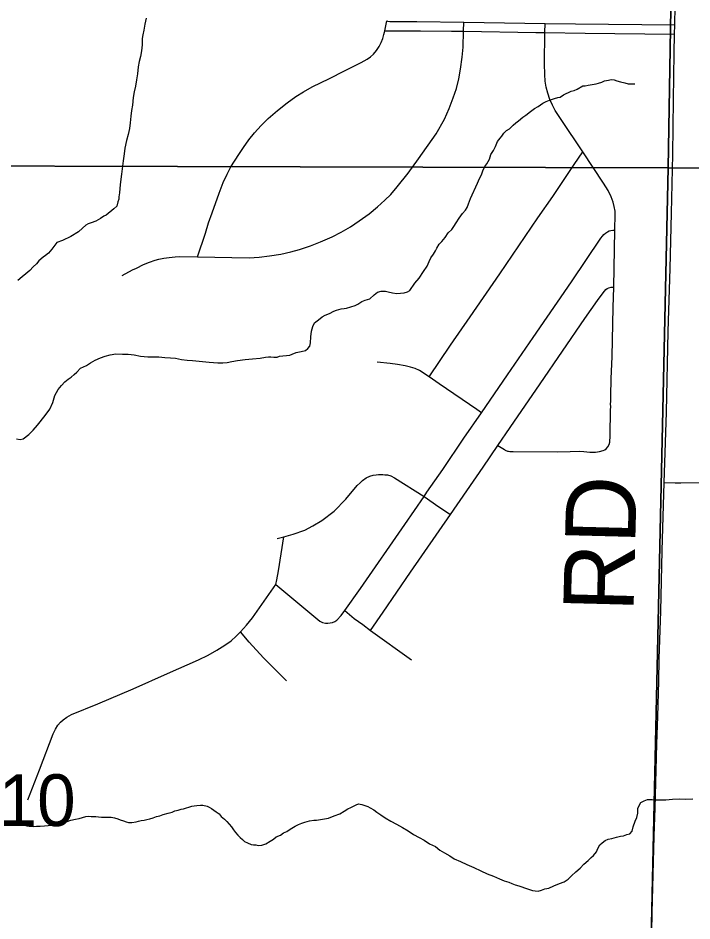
# Model space of a CAD drawing. Extents: x 2.4 to 73.1, y 4.5 to 25.6.
# Drawn here: x 35.324 to 35.5963, y 23.7807 to 24.1457 of the extents above; entities that cross this region are included whole.
import ezdxf

# ---------------------------------------------------------------- set-up
doc = ezdxf.new("R2010")
doc.units = 0
for name, color, linetype in [('GM_X_Minor_River', 7, 'Continuous'), ('GM_X_Section', 7, 'Continuous'), ('GM_X_Section_Text', 7, 'Continuous'), ('GM_X_Township_Road', 7, 'Continuous'), ('GM_X_Township_Road_Text', 7, 'Continuous')]:
    doc.layers.add(name, color=color, linetype=linetype)

msp = doc.modelspace()

# ---------------------------------------------------------------- linework, layer by layer
at = {"layer": 'GM_X_Minor_River'}
for points in [[(35.37569, 24.14575), (35.37525, 24.14329), (35.37481, 24.14083), (35.37438, 24.13895), (35.37415, 24.13743), (35.37409, 24.13497), (35.37384, 24.1325), (35.3734, 24.13024), (35.37297, 24.12816), (35.37254, 24.12608), (35.37228, 24.12324), (35.37183, 24.12078), (35.37139, 24.11814), (35.37095, 24.11587), (35.37051, 24.1136), (35.37025, 24.11057), (35.36981, 24.1083), (35.36956, 24.10603), (35.36931, 24.10338), (35.36906, 24.10111), (35.36843, 24.09865), (35.3678, 24.0962), (35.36715, 24.09318), (35.3669, 24.09091), (35.36645, 24.08807), (35.36621, 24.0858), (35.36575, 24.08258), (35.36526, 24.07842)], [(35.506, 24.07067), (35.50681, 24.07274), (35.50963, 24.07893), (35.51043, 24.08081), (35.51123, 24.08231), (35.51184, 24.084), (35.51265, 24.08569), (35.51343, 24.08681), (35.51443, 24.08868), (35.51505, 24.09057), (35.51604, 24.09225), (35.51684, 24.09375), (35.51765, 24.09582), (35.51882, 24.09712), (35.51941, 24.09805), (35.5202, 24.09917), (35.52137, 24.10028), (35.52253, 24.10101), (35.52409, 24.10249), (35.52506, 24.10341), (35.52622, 24.10415), (35.52796, 24.10562), (35.52913, 24.10654), (35.53106, 24.10801), (35.53261, 24.10911), (35.53415, 24.11002), (35.53608, 24.1113), (35.53743, 24.11202), (35.53877, 24.11256), (35.54069, 24.11327), (35.54203, 24.11362), (35.54298, 24.11378), (35.54434, 24.1147), (35.54549, 24.11524), (35.54645, 24.11559), (35.54741, 24.11614), (35.54875, 24.11649), (35.5499, 24.11702), (35.55221, 24.1183), (35.55316, 24.11827), (35.55431, 24.11862), (35.55755, 24.11911), (35.55851, 24.11947), (35.55985, 24.11981), (35.561, 24.12035), (35.56253, 24.12069), (35.56367, 24.12085), (35.56481, 24.12082), (35.56594, 24.12042), (35.56745, 24.12), (35.56915, 24.11958), (35.57047, 24.11916), (35.5718, 24.11913), (35.5732, 24.11909)], [(35.36526, 24.07842), (35.36498, 24.07501), (35.36476, 24.07349), (35.36473, 24.07255), (35.36432, 24.07142), (35.3639, 24.06972), (35.36273, 24.06861), (35.35963, 24.06603), (35.35867, 24.06567), (35.35732, 24.06476), (35.35539, 24.06367), (35.35347, 24.06296), (35.35233, 24.06261), (35.35136, 24.06206), (35.35, 24.06077), (35.34844, 24.05929), (35.34536, 24.05747), (35.3419, 24.05585), (35.3396, 24.05496), (35.33763, 24.05235), (35.33626, 24.05067), (35.3351, 24.04975), (35.33413, 24.04902), (35.33238, 24.04754), (35.3314, 24.04643), (35.33004, 24.04514), (35.32867, 24.04365), (35.32712, 24.04236), (35.32557, 24.04107), (35.32382, 24.0396)], [(35.34428, 23.99978), (35.34544, 24.00051), (35.34661, 24.00162), (35.34777, 24.00254), (35.34914, 24.00421), (35.35164, 24.00529), (35.35319, 24.00639), (35.35511, 24.00748), (35.35723, 24.00837), (35.35914, 24.00908), (35.36125, 24.0096), (35.36353, 24.00992), (35.36619, 24.00985), (35.36847, 24.00979), (35.37093, 24.00954), (35.37339, 24.0091), (35.37642, 24.00883), (35.37851, 24.00878), (35.38079, 24.00872), (35.38325, 24.00847), (35.38553, 24.00841), (35.38761, 24.00817), (35.39007, 24.00773), (35.39234, 24.00748), (35.39442, 24.00724), (35.40125, 24.00668), (35.40466, 24.00641), (35.40675, 24.00636), (35.40846, 24.0065), (35.41037, 24.00683), (35.41266, 24.00734), (35.41571, 24.00765), (35.41876, 24.00795), (35.4218, 24.00825), (35.4239, 24.00858), (35.42523, 24.00874), (35.42618, 24.00871), (35.42732, 24.00868), (35.42865, 24.00865), (35.42961, 24.009), (35.43094, 24.00916), (35.43246, 24.00931), (35.4338, 24.00947), (35.43476, 24.00982), (35.4363, 24.01054), (35.43839, 24.01087), (35.44012, 24.01139), (35.44108, 24.01213), (35.44187, 24.01306), (35.44209, 24.01438), (35.44234, 24.01684), (35.44259, 24.01912), (35.4428, 24.02006), (35.44302, 24.021), (35.44381, 24.0225), (35.44537, 24.02379), (35.44691, 24.02489), (35.44807, 24.02562), (35.4498, 24.02634), (35.45153, 24.02724), (35.45268, 24.02759), (35.45459, 24.02811), (35.45574, 24.02828), (35.45669, 24.02844), (35.46014, 24.02949), (35.46129, 24.03003), (35.46284, 24.03113), (35.46418, 24.03167), (35.46609, 24.03219), (35.46784, 24.03385), (35.4692, 24.03496), (35.47073, 24.0353), (35.47244, 24.03526), (35.47357, 24.03504), (35.47527, 24.03461), (35.47697, 24.03438), (35.4785, 24.03453), (35.48002, 24.03468), (35.48136, 24.03503), (35.48232, 24.03557), (35.4843, 24.03856), (35.48606, 24.04061), (35.48783, 24.04322), (35.48922, 24.04546), (35.49003, 24.04734), (35.49082, 24.04884), (35.49181, 24.05033), (35.4926, 24.05164), (35.4932, 24.05277), (35.49419, 24.05426), (35.49517, 24.05538), (35.49654, 24.05705), (35.49773, 24.05892), (35.49928, 24.06021), (35.50007, 24.06152), (35.50106, 24.06301), (35.50224, 24.06488), (35.50362, 24.06674), (35.50479, 24.06804), (35.50539, 24.06917), (35.506, 24.07067)], [(35.32335, 23.97563), (35.32486, 23.9754), (35.32601, 23.97556), (35.32833, 23.9774), (35.33008, 23.97906), (35.33185, 23.98111), (35.33498, 23.98502), (35.33676, 23.98763), (35.33796, 23.99025), (35.3388, 23.99308), (35.34019, 23.99551), (35.34156, 23.99719), (35.34293, 23.99867), (35.34428, 23.99978)], [(35.43736, 23.81972), (35.4387, 23.82026), (35.43985, 23.82061), (35.44081, 23.82097), (35.44176, 23.82113), (35.44348, 23.82147), (35.44462, 23.82144), (35.44939, 23.82227), (35.45169, 23.82316), (35.45399, 23.82405), (35.45573, 23.82514), (35.45727, 23.82605), (35.45843, 23.82659), (35.45958, 23.82713), (35.46054, 23.82768), (35.4615, 23.82803), (35.46283, 23.82781), (35.46415, 23.8274), (35.46527, 23.82699), (35.46621, 23.8264), (35.46771, 23.8256), (35.46901, 23.82462), (35.47051, 23.82363), (35.47238, 23.82244), (35.47462, 23.82106), (35.47687, 23.81986), (35.4793, 23.81847), (35.48155, 23.81709), (35.48379, 23.8157), (35.48604, 23.8145), (35.4881, 23.81331), (35.49016, 23.81193), (35.49259, 23.81073), (35.49446, 23.80936), (35.49633, 23.80817), (35.49839, 23.80698), (35.50026, 23.80579), (35.5027, 23.80478), (35.50533, 23.80357), (35.50815, 23.80236), (35.51096, 23.80096), (35.51359, 23.79976), (35.51603, 23.79875), (35.51848, 23.79774), (35.52035, 23.79693), (35.52224, 23.79631), (35.52356, 23.7959), (35.52487, 23.7953), (35.52638, 23.79488), (35.52751, 23.79447), (35.52864, 23.79406), (35.53184, 23.79303), (35.53298, 23.79281), (35.53412, 23.79278), (35.53545, 23.79313), (35.5368, 23.79366), (35.53851, 23.794), (35.54044, 23.7949), (35.54274, 23.79579), (35.54466, 23.7965), (35.5462, 23.7976), (35.54757, 23.7989), (35.54932, 23.80056), (35.55106, 23.80203), (35.55263, 23.8037), (35.55437, 23.80518), (35.55554, 23.80629), (35.55651, 23.80721), (35.55769, 23.8087), (35.55829, 23.81001), (35.55909, 23.81151), (35.56006, 23.81225), (35.56122, 23.81316), (35.56238, 23.81371), (35.5639, 23.81405), (35.56582, 23.81457), (35.56734, 23.81491), (35.56868, 23.81506), (35.57002, 23.8156), (35.57117, 23.81595), (35.57215, 23.81706), (35.57257, 23.81876), (35.57339, 23.82102), (35.574, 23.82252), (35.57442, 23.82422), (35.57447, 23.82612), (35.57507, 23.82762), (35.57567, 23.82855), (35.57702, 23.82928), (35.57836, 23.82982), (35.57931, 23.82979), (35.58026, 23.82977), (35.58159, 23.82973), (35.58348, 23.82968), (35.58576, 23.82963), (35.58843, 23.82994), (35.59109, 23.83006), (35.59375, 23.82999), (35.5966, 23.83011)], [(35.32304, 23.82073), (35.32436, 23.82013), (35.3253, 23.81972), (35.32643, 23.8195), (35.32756, 23.8191), (35.32851, 23.81907), (35.33002, 23.81884), (35.33136, 23.819), (35.33287, 23.81896), (35.33459, 23.81911), (35.33611, 23.81926), (35.33744, 23.81941), (35.33878, 23.81976), (35.33993, 23.81992), (35.34107, 23.82027), (35.34222, 23.82062), (35.34375, 23.82096), (35.34528, 23.82149), (35.34719, 23.82182), (35.34872, 23.82216), (35.35006, 23.82251), (35.3514, 23.82286), (35.35235, 23.82302), (35.35349, 23.82299), (35.35539, 23.82294), (35.35652, 23.82273), (35.35766, 23.8227), (35.35937, 23.82265), (35.3607, 23.82262), (35.36165, 23.8226), (35.36297, 23.82237), (35.36429, 23.82196), (35.36523, 23.82156), (35.36655, 23.82114), (35.36768, 23.82074), (35.36862, 23.82052), (35.36995, 23.82049), (35.37167, 23.82082), (35.37262, 23.82099), (35.37377, 23.82134), (35.37492, 23.8215), (35.37606, 23.82166), (35.37721, 23.82201), (35.37855, 23.82236), (35.37989, 23.82289), (35.38123, 23.82324), (35.38257, 23.82377), (35.38467, 23.82429), (35.3862, 23.82463), (35.38735, 23.82517), (35.38869, 23.82552), (35.38984, 23.82587), (35.39079, 23.82603), (35.39424, 23.82708), (35.39519, 23.82725), (35.39615, 23.82741), (35.39767, 23.82757), (35.39862, 23.82754), (35.40032, 23.82712), (35.40126, 23.82672), (35.40219, 23.82612), (35.40313, 23.82553), (35.40406, 23.82475), (35.40518, 23.82396), (35.4061, 23.82299), (35.4074, 23.82181), (35.40833, 23.82084), (35.40925, 23.81987), (35.41017, 23.81871), (35.41109, 23.81754), (35.41182, 23.81639), (35.41275, 23.81541), (35.41367, 23.81444), (35.4146, 23.81366), (35.41553, 23.81288), (35.41666, 23.81228), (35.41816, 23.81167), (35.41911, 23.81146), (35.42006, 23.81143), (35.421, 23.81122), (35.42252, 23.81137), (35.42406, 23.8119), (35.42579, 23.813), (35.42714, 23.81372), (35.4283, 23.81464), (35.43003, 23.81536), (35.43119, 23.81628), (35.43254, 23.81681), (35.43351, 23.81755), (35.43466, 23.81827), (35.43601, 23.819), (35.43736, 23.81972)]]:
    msp.add_lwpolyline(points, dxfattribs=at)
at = {"layer": 'GM_X_Section'}
for points in [[(35.09559, 24.58561), (35.59489, 24.57543), (35.58661, 24.08517), (35.09073, 24.08656)], [(35.59489, 24.57543), (36.09659, 24.5645), (36.08619, 24.08472), (35.58661, 24.08517)], [(35.09073, 24.08656), (35.58661, 24.08517), (35.57563, 23.58341), (35.07727, 23.59263)], [(35.58661, 24.08517), (36.08619, 24.08472), (36.07683, 23.58085), (35.57563, 23.58341)]]:
    msp.add_lwpolyline(points, close=True, dxfattribs=at)
at = {"layer": 'GM_X_Township_Road'}
for p, q in [((35.50396, 24.14039), (35.50404, 24.1441)), ((35.53689, 24.13988), (35.53698, 24.1436)), ((35.58926, 24.13918), (35.58934, 24.14294)), ((35.56465, 24.03687), (35.56515, 24.05999)), ((35.46634, 23.89809), (35.48297, 23.88621))]:
    msp.add_line(p, q, dxfattribs=at)
for points in [[(35.58934, 24.14294), (35.58949, 24.15052), (35.58995, 24.17694), (35.59055, 24.20802), (35.59085, 24.22667), (35.59132, 24.25589), (35.59155, 24.27391), (35.5918, 24.28571), (35.59214, 24.31072)], [(35.47213, 24.14058), (35.47284, 24.14391), (35.47299, 24.1446)], [(35.47299, 24.1446), (35.47332, 24.14447), (35.47421, 24.14433), (35.47643, 24.14435), (35.48508, 24.14433), (35.50404, 24.1441), (35.53698, 24.1436), (35.54919, 24.14344), (35.58934, 24.14294)], [(35.39654, 24.04917), (35.39966, 24.05883), (35.40098, 24.06296), (35.40245, 24.06705), (35.40521, 24.07496), (35.40689, 24.07929), (35.40841, 24.08266), (35.41, 24.08564), (35.41315, 24.09061), (35.41504, 24.09344), (35.41719, 24.09645), (35.41952, 24.09933), (35.42222, 24.10229), (35.42509, 24.1051), (35.42881, 24.10837), (35.43266, 24.11148), (35.43617, 24.11399), (35.43931, 24.11596), (35.44283, 24.11789), (35.44979, 24.12133), (35.45588, 24.12444), (35.46257, 24.12775), (35.46506, 24.12913), (35.46637, 24.13006), (35.46755, 24.13115), (35.46881, 24.1326), (35.46988, 24.1342), (35.47075, 24.1359), (35.47139, 24.13752), (35.47177, 24.13905), (35.47202, 24.14005), (35.47213, 24.14058)], [(35.39654, 24.04917), (35.41734, 24.04886), (35.42134, 24.04908), (35.42564, 24.04958), (35.43021, 24.05033), (35.43413, 24.05119), (35.4377, 24.05219), (35.44209, 24.05367), (35.44612, 24.05524), (35.45094, 24.05735), (35.45452, 24.05916), (35.45826, 24.06133), (35.46187, 24.0637), (35.46585, 24.06664), (35.46922, 24.06936), (35.47219, 24.07205), (35.47457, 24.07446), (35.47721, 24.07749), (35.48162, 24.08308), (35.48584, 24.08884), (35.49298, 24.09898), (35.49628, 24.10489), (35.49817, 24.10912), (35.49984, 24.11345), (35.50107, 24.11726), (35.50206, 24.12115), (35.50281, 24.12509), (35.50348, 24.12999), (35.50381, 24.13399), (35.50396, 24.14039)], [(35.47213, 24.14058), (35.47379, 24.14058), (35.48661, 24.14061), (35.4991, 24.14047), (35.50396, 24.14039)], [(35.50396, 24.14039), (35.53325, 24.13993), (35.53689, 24.13988)], [(35.55225, 24.0916), (35.54338, 24.10479), (35.54105, 24.10843), (35.53988, 24.11057), (35.53889, 24.11281), (35.53798, 24.11542), (35.53736, 24.11778), (35.53699, 24.12019), (35.53679, 24.12294), (35.53669, 24.12729), (35.53689, 24.13988)], [(35.53689, 24.13988), (35.55313, 24.13969), (35.58926, 24.13918)], [(35.58504, 23.9579), (35.58513, 23.96188), (35.58593, 23.98643), (35.58672, 24.01906), (35.58745, 24.04454), (35.58802, 24.06692), (35.58849, 24.09054), (35.58879, 24.11269), (35.58913, 24.13157), (35.58926, 24.13918)], [(35.49006, 24.00067), (35.49874, 24.01345), (35.50666, 24.02495), (35.51859, 24.04238), (35.53398, 24.06503), (35.54003, 24.07364), (35.54872, 24.08652), (35.55225, 24.0916)], [(35.56515, 24.05999), (35.56529, 24.06649), (35.56524, 24.06761), (35.56491, 24.06949), (35.5644, 24.07133), (35.56362, 24.0734), (35.56237, 24.07596), (35.5606, 24.07892), (35.55225, 24.0916)], [(35.51124, 23.98615), (35.52176, 24.00143), (35.53211, 24.01657), (35.54756, 24.03916), (35.5595, 24.05676), (35.56016, 24.05759), (35.56069, 24.0582), (35.56139, 24.05882), (35.56213, 24.05936), (35.56287, 24.05974), (35.56354, 24.0599), (35.56433, 24.06), (35.56515, 24.05999)], [(35.36602, 24.04167), (35.37021, 24.04392), (35.37187, 24.04467), (35.37469, 24.04606), (35.37704, 24.04698), (35.37943, 24.04782), (35.38091, 24.04823), (35.38288, 24.04864), (35.38502, 24.04898), (35.38741, 24.04922), (35.38937, 24.0493), (35.39654, 24.04917)], [(35.51789, 23.97298), (35.52278, 23.98015), (35.53493, 23.99785), (35.55306, 24.02427), (35.55814, 24.03161), (35.55962, 24.03361), (35.56094, 24.03538), (35.56149, 24.03594), (35.56205, 24.03634), (35.56269, 24.03667), (35.56367, 24.03688), (35.56465, 24.03687)], [(35.51789, 23.97298), (35.52048, 23.97126), (35.52077, 23.97107), (35.52174, 23.97066), (35.52212, 23.97066), (35.52273, 23.97053), (35.52336, 23.97048), (35.524, 23.97048), (35.54204, 23.97042), (35.54703, 23.97054), (35.55071, 23.97062), (35.55254, 23.97047), (35.55506, 23.97026), (35.55729, 23.97027), (35.55888, 23.97045), (35.56046, 23.97085), (35.56112, 23.97116), (35.56168, 23.97161), (35.56234, 23.97242), (35.56279, 23.97335), (35.56303, 23.97433), (35.5632, 23.97687), (35.56337, 23.98744), (35.56345, 23.98836), (35.56341, 23.98993), (35.56345, 23.99054), (35.56349, 23.99303), (35.5637, 23.99985), (35.56399, 24.00886), (35.56439, 24.02873), (35.56465, 24.03687)], [(35.49006, 24.00067), (35.48616, 24.00324), (35.48439, 24.00403), (35.48258, 24.00466), (35.48043, 24.00518), (35.47732, 24.00569), (35.47429, 24.00606), (35.46902, 24.00664)], [(35.51124, 23.98615), (35.50934, 23.98744), (35.4942, 23.99784), (35.49006, 24.00067)], [(35.48807, 23.95235), (35.4892, 23.95401), (35.49556, 23.96322), (35.50413, 23.97582), (35.51124, 23.98615)], [(35.49865, 23.94502), (35.51192, 23.96421), (35.51789, 23.97298)], [(35.42862, 23.93536), (35.43138, 23.93594), (35.43518, 23.93702), (35.43979, 23.93875), (35.44308, 23.94039), (35.44674, 23.9426), (35.45171, 23.9464), (35.45639, 23.95118), (35.46106, 23.95669), (35.46215, 23.95787), (35.46315, 23.95871), (35.46465, 23.9598), (35.46613, 23.9605), (35.46749, 23.96087), (35.46868, 23.96108), (35.46959, 23.9612), (35.47049, 23.9612), (35.47135, 23.96116), (35.47218, 23.96112), (35.47325, 23.961), (35.47455, 23.96064), (35.47609, 23.95985), (35.48807, 23.95235)], [(35.58004, 23.77619), (35.58021, 23.78395), (35.58105, 23.81502), (35.5814, 23.82649), (35.58188, 23.84172), (35.58214, 23.85228), (35.58248, 23.86342), (35.58286, 23.87768), (35.58304, 23.88669), (35.58364, 23.90596), (35.58423, 23.93035), (35.58504, 23.9579)], [(35.58504, 23.9579), (35.58945, 23.95788), (35.5918, 23.95787), (35.61467, 23.95797)], [(35.45606, 23.90617), (35.46239, 23.91509), (35.48025, 23.94092), (35.48807, 23.95235)], [(35.48807, 23.95235), (35.49394, 23.94814), (35.49865, 23.94502)], [(35.46634, 23.89809), (35.47146, 23.90556), (35.4826, 23.92169), (35.49865, 23.94502)], [(35.4281, 23.91673), (35.4285, 23.91858), (35.42918, 23.92224), (35.43138, 23.93594)], [(35.41388, 23.89756), (35.41631, 23.90032), (35.41871, 23.90324), (35.4281, 23.91673)], [(35.4281, 23.91673), (35.44596, 23.90196), (35.44702, 23.9013), (35.44822, 23.90107), (35.44911, 23.90106), (35.45009, 23.90116), (35.45102, 23.90142), (35.45193, 23.90178), (35.45274, 23.90237), (35.45459, 23.90425), (35.45606, 23.90617)], [(35.45606, 23.90617), (35.45977, 23.90303), (35.46323, 23.9005), (35.46634, 23.89809)], [(35.3279, 23.82963), (35.33264, 23.84182), (35.33815, 23.85631), (35.33907, 23.85826), (35.34006, 23.85982), (35.34106, 23.861), (35.3422, 23.86204), (35.34371, 23.86311), (35.34562, 23.86415), (35.35623, 23.86853), (35.37055, 23.87455), (35.38442, 23.88079), (35.39692, 23.8863), (35.40082, 23.88822), (35.40435, 23.89017), (35.4075, 23.89216), (35.41002, 23.89399), (35.41213, 23.89581), (35.41388, 23.89756)], [(35.43239, 23.8778), (35.42311, 23.88712), (35.41732, 23.89342), (35.41388, 23.89756)]]:
    msp.add_lwpolyline(points, dxfattribs=at)

# ---------------------------------------------------------------- texts
at = {"layer": 'GM_X_Section_Text'}
msp.add_text('10', height=0.020928, rotation=0, dxfattribs=at).set_placement((35.31611, 23.81907))
at = {"layer": 'GM_X_Township_Road_Text'}
msp.add_text('RD', height=0.028409, rotation=88.5311, dxfattribs=at).set_placement((35.57264, 23.90541))

doc.saveas('drawing.dxf')
